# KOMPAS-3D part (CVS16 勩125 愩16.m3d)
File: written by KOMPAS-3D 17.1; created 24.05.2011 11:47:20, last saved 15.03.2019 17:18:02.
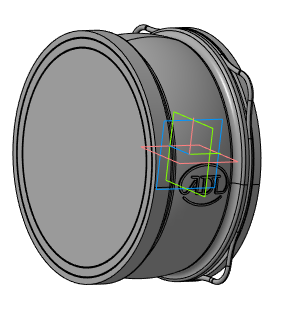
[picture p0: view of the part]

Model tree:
1. Плоскость XY
2. Плоскость ZX
3. Плоскость ZY
4. Ось X
5. Ось Y
6. Ось Z
7. Начало координат
8. Операция без истории:3
9. Операция без истории:4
